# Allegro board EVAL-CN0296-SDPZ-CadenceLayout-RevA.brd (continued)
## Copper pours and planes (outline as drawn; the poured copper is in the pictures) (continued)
IOVDD on L3_PWR: 18.41,29.21 18.41,34.29 1.27,34.29 1.27,85.09 6.99,85.09 6.99,91.44 1.27,91.44 1.27,92.71 92.71,92.71 92.71,92.08 86.36,92.08 86.36,83.82 92.71,83.82 92.71,29.21 ; 3 cut-outs
UNNAMED_4_CAP4PV3_I13_IN on TOP: 20.19,11.94 24.51,11.94 24.51,9.53 23.5,8.51 20.57,8.51 20.57,9.65 20.19,10.03
UNNAMED_4_CAP4PV3_I13_OUT on TOP: 23.5,15.88 24.77,15.88 24.77,13.59 24.64,13.46 23.62,13.46 23.5,13.59
UNNAMED_4_CAP_I6_N1 on TOP: 13.46,13.21 13.46,14.48 15.37,16.38 21.21,16.38 21.84,15.75 21.84,13.46 19.68,13.46 19.3,13.08 17.27,13.08 17.27,10.67 16,10.67

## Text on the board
Ref Des/Silkscreen Top: GND | VIN | IOVDD | SDATA | BCLK | LRCLK | MCLK | OUTR4 | OUTL4 | OUTR3 | OUTL3 | OUTR2 | OUTL2 | OUTR1 | OUTL1 | REV A | EVAL-CN0296-SDPZ
DIMENSION: REF
PAGE_OUTLINE: J. CHUA | 11DEC12 | N/A | ADAU1761 & SSM2518
DISPLAY_BOTTOM: L2 DGND | 08-      -07
User.6: L3 PWR | 08-      -08
User.7: ROHS COMPLIANCE NOTE:  (Required for Customer Boards) Add to top of MATERIALS | 100 MICRO INCHES NICKEL/ | 3-5 MICRO INCHES GOLD | HOMOGENOUS MATERIALS IN THIS BOARD SHALL BE COMPLIANT | THE EU RoHS DIRECTIVE 2002/95/EC | 50 OHMS SINGLE ENDED, 15 MILS LINE
User.11: L4 SIG
User.12: L5 PWR
User.21: FIGURE | SIZE | 12.0 | 35.0 | 40.0 | 45.0 | 63.0 | 120.0 | 140.0 | 28.0 | 43.0 | 67.0 | 125.0 | 136.0 | DRILL CHART: TOP to BOTTOM | ALL UNITS ARE IN MILS | TOLERANCE | +3.0/-3.0 | +2.0/-2.0 | PLATED | NON-PLATED | QTY | 443 | 2 | 38 | 10 | 14 | 1 | 4 | 3
